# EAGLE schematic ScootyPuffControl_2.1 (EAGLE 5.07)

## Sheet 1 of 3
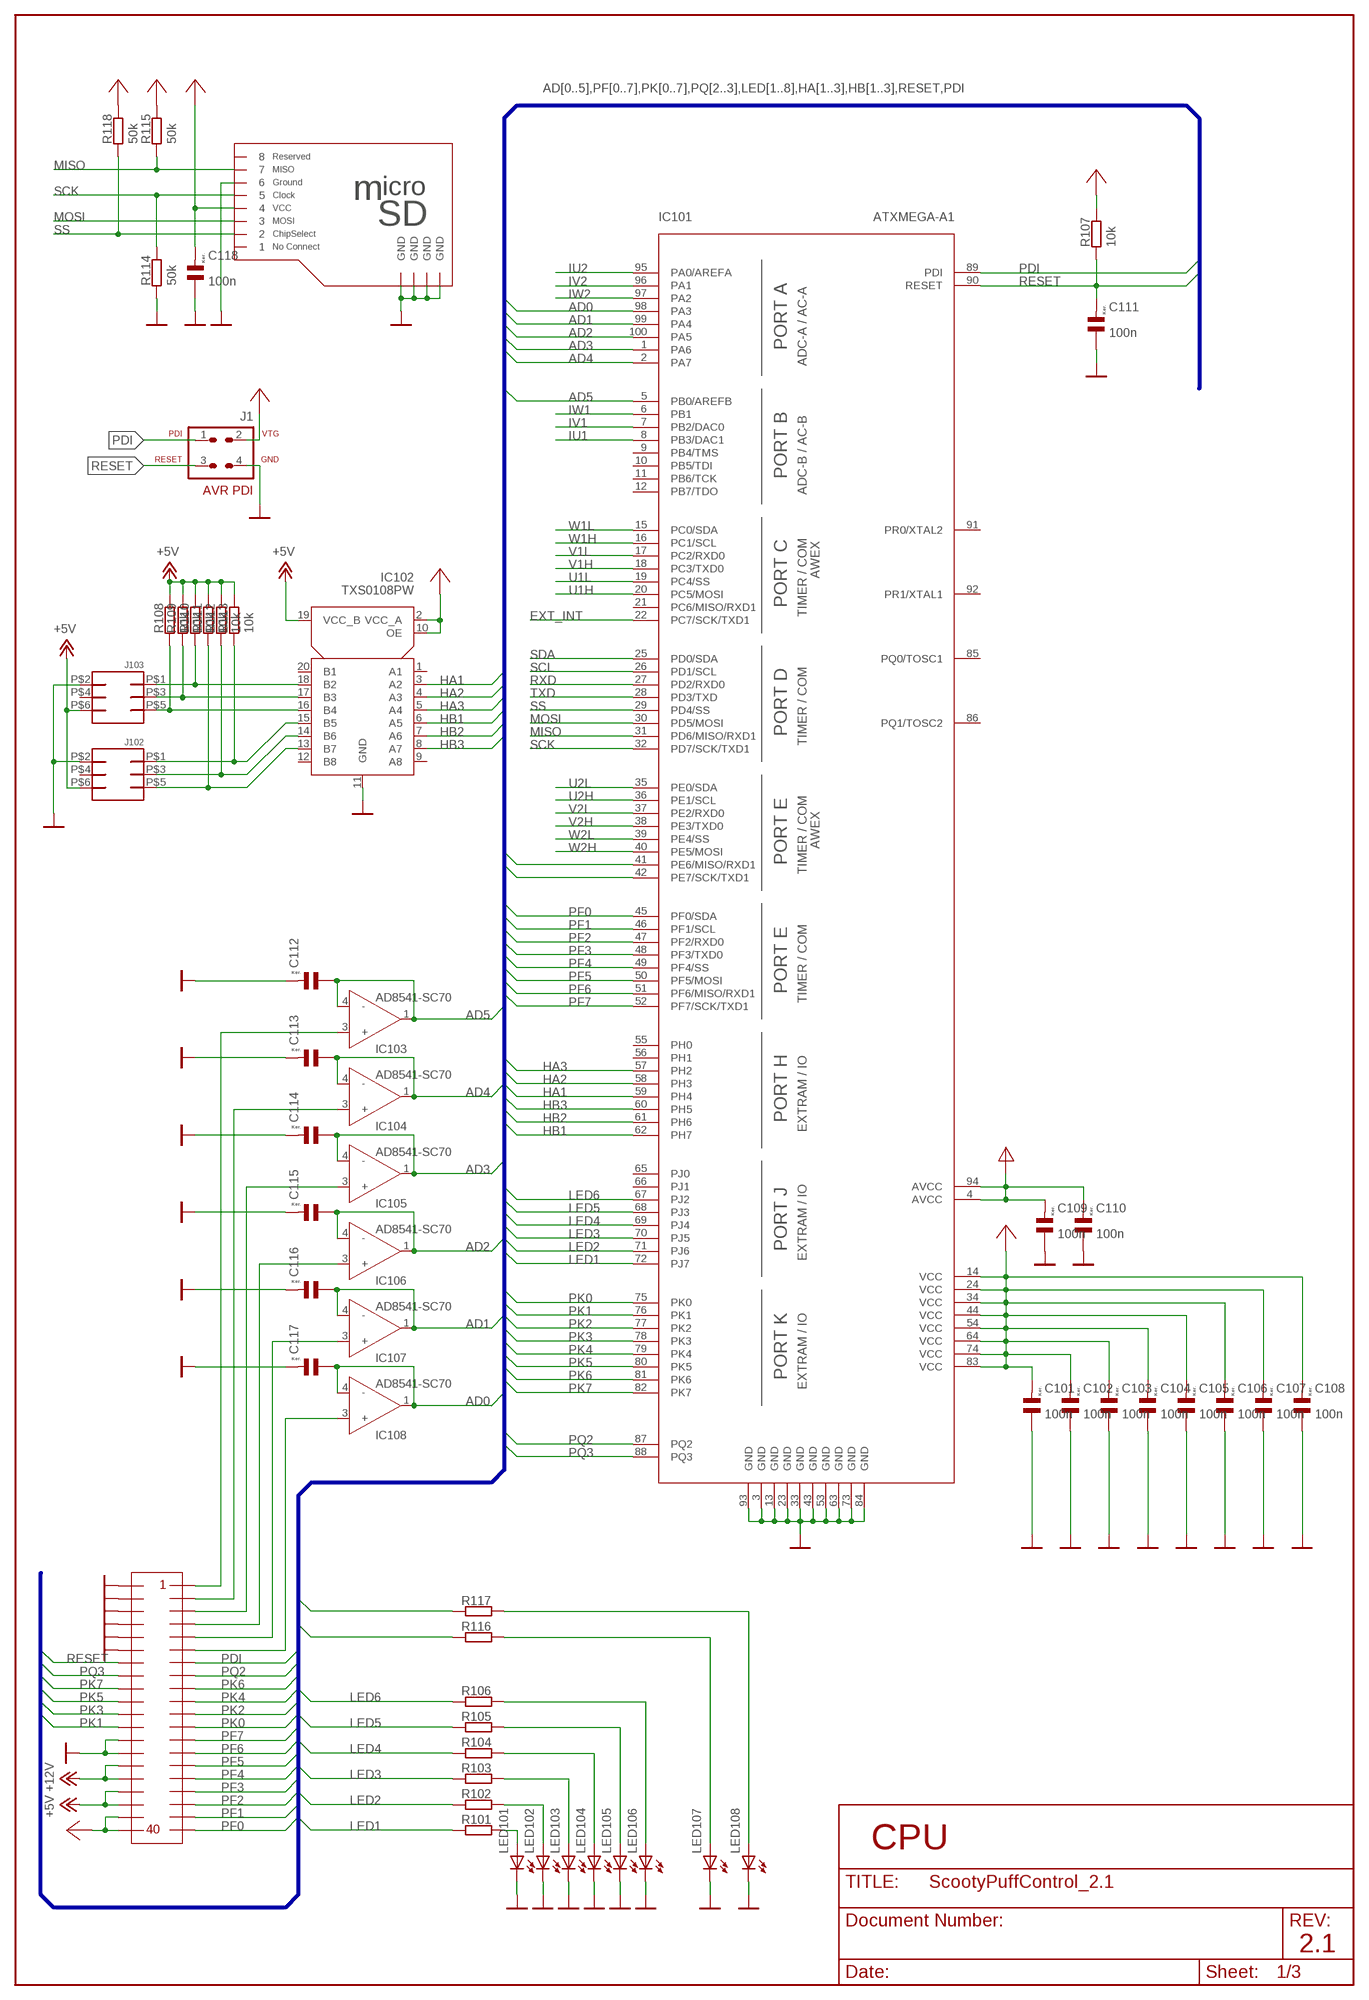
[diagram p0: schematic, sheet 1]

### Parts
C101  100n  C_KER_0805  [C0805K]
C102  100n  C_KER_0805  [C0805K]
C103  100n  C_KER_0805  [C0805K]
C104  100n  C_KER_0805  [C0805K]
C105  100n  C_KER_0805  [C0805K]
C106  100n  C_KER_0805  [C0805K]
C107  100n  C_KER_0805  [C0805K]
C108  100n  C_KER_0805  [C0805K]
C109  100n  C_KER_0805  [C0805K]
C110  100n  C_KER_0805  [C0805K]
C111  100n  C_KER_0805  [C0805K]
C112  C_KER_0603  [C0603K]
C113  C_KER_0603  [C0603K]
C114  C_KER_0603  [C0603K]
C115  C_KER_0603  [C0603K]
C116  C_KER_0603  [C0603K]
C117  C_KER_0603  [C0603K]
C118  100n  C_KER_0805  [C0805K]
IC101  ATXMEGA-A1  [TQFP100]
IC102  TXS0108PW  TXB0108PW  [TSSOP20]
IC103  AD8541-SC70  [SC70-5L]
IC104  AD8541-SC70  [SC70-5L]
IC105  AD8541-SC70  [SC70-5L]
IC106  AD8541-SC70  [SC70-5L]
IC107  AD8541-SC70  [SC70-5L]
IC108  AD8541-SC70  [SC70-5L]
J1  AVR-PDIMM04  [SMDTOP4]
J100  SCOOTYPUFF_EXTENSION  SCOOTYPUFF_EXTENSION_SMT  [SCOOTYPUFF_EXTENSION_SMT]
J102  SL6X2_SL  [SL2X3G_SMD254@1]
J103  SL6X2_SL  [SL2X3G_SMD254@1]
J104  MICRO_SD_ST1  [JAE_ST1_MICOSD]
LED101  LEDCHIP-LED0805  [CHIP-LED0805]
LED102  LEDCHIP-LED0805  [CHIP-LED0805]
LED103  LEDCHIP-LED0805  [CHIP-LED0805]
LED104  LEDCHIP-LED0805  [CHIP-LED0805]
LED105  LEDCHIP-LED0805  [CHIP-LED0805]
LED106  LEDCHIP-LED0805  [CHIP-LED0805]
LED107  LEDCHIP-LED0805  [CHIP-LED0805]
LED108  LEDCHIP-LED0805  [CHIP-LED0805]
R101  R_0805  [R0805]
R102  R_0805  [R0805]
R103  R_0805  [R0805]
R104  R_0805  [R0805]
R105  R_0805  [R0805]
R106  R_0805  [R0805]
R107  10k  R_0805  [R0805]
R108  10k  R_0603  [R0603]
R109  10k  R_0603  [R0603]
R110  10k  R_0603  [R0603]
R111  10k  R_0603  [R0603]
R112  10k  R_0603  [R0603]
R113  10k  R_0603  [R0603]
R114  50k  R_0805  [R0805]
R115  50k  R_0805  [R0805]
R116  R_0805  [R0805]
R117  R_0805  [R0805]
R118  50k  R_0805  [R0805]

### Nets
+5V: IC102.19(VCC_B) J100.P$34 J100.P$36 J102.P$6 J103.P$6 R108.2 R109.2 R110.2 R111.2 R112.2 R113.2 ; also sheet 3
+12V: J100.P$30 J100.P$32 ; also sheet 2,3
AD0: C117.1 IC101.98(PA3) IC108.1(O) IC108.4(-)
AD1: C116.1 IC101.99(PA4) IC107.1(O) IC107.4(-)
AD2: C115.1 IC101.100(PA5) IC106.1(O) IC106.4(-)
AD3: C114.1 IC101.1(PA6) IC105.1(O) IC105.4(-)
AD4: C113.1 IC101.2(PA7) IC104.1(O) IC104.4(-)
AD5: C112.1 IC101.5(PB0/AREFB) IC103.1(O) IC103.4(-)
AVCC: C109.2 C110.2 IC101.4(AVCC) IC101.94(AVCC) ; also sheet 3
EXT_INT: IC101.22(PC7/SCK/TXD1) ; also sheet 3
GND: C101.1 C102.1 C103.1 C104.1 C105.1 C106.1 C107.1 C108.1 C109.1 C110.1 C111.1 C112.2 C113.2 C114.2 C115.2 C116.2 C117.2 C118.1 IC101.3(GND) IC101.13(GND) IC101.23(GND) IC101.33(GND) IC101.43(GND) IC101.53(GND) IC101.63(GND) IC101.73(GND) IC101.84(GND) IC101.93(GND) IC102.11(GND) J1.4(GND) J100.P$2 J100.P$4 J100.P$6 J100.P$8 J100.P$10 J100.P$12 J100.P$26 J100.P$28 J102.P$2 J103.P$2 J104.6 J104.GND1(GND) J104.GND2(GND) J104.GND3(GND) J104.GND4(GND) LED101.C LED102.C LED103.C LED104.C LED105.C LED106.C LED107.C LED108.C R114.1 ; also sheet 2,3
HA1: IC101.59(PH4) IC102.3(A2)
HA2: IC101.58(PH3) IC102.4(A3)
HA3: IC101.57(PH2) IC102.5(A4)
HB1: IC101.62(PH7) IC102.6(A5)
HB2: IC101.61(PH6) IC102.7(A6)
HB3: IC101.60(PH5) IC102.8(A7)
IU1: IC101.8(PB3/DAC1) ; also sheet 2
IU2: IC101.95(PA0/AREFA) ; also sheet 2
IV1: IC101.7(PB2/DAC0) ; also sheet 2
IV2: IC101.96(PA1) ; also sheet 2
IW1: IC101.6(PB1) ; also sheet 2
IW2: IC101.97(PA2) ; also sheet 2
LED1: IC101.72(PJ7) R101.2
LED2: IC101.71(PJ6) R102.2
LED3: IC101.70(PJ5) R103.2
LED4: IC101.69(PJ4) R104.2
LED5: IC101.68(PJ3) R105.2
LED6: IC101.67(PJ2) R106.2
LED7: IC101.41(PE6/MISO/RXD1) R116.2
LED8: IC101.42(PE7/SCK/TXD1) R117.2
MISO: IC101.31(PD6/MISO/RXD1) J104.7 R115.1
MOSI: IC101.30(PD5/MOSI) J104.3
N$1: LED107.A R116.1
N$2: LED108.A R117.1
N$21: IC107.3(+) J100.P$9
N$35: IC102.18(B2) J103.P$1 R110.1
N$36: IC102.16(B4) J103.P$5 R108.1
N$37: IC102.17(B3) J103.P$3 R109.1
N$39: IC102.15(B5) J102.P$1 R113.1
N$40: IC102.14(B6) J102.P$3 R112.1
N$41: IC102.13(B7) J102.P$5 R111.1
N$63: LED101.A R101.1
N$64: IC108.3(+) J100.P$11
N$65: IC106.3(+) J100.P$7
N$66: IC105.3(+) J100.P$5
N$67: IC104.3(+) J100.P$3
N$68: IC103.3(+) J100.P$1
N$70: LED102.A R102.1
N$71: LED103.A R103.1
N$72: LED104.A R104.1
N$73: LED105.A R105.1
N$74: LED106.A R106.1
PDI: IC101.89(PDI) J1.1(PDI) J100.P$13
PF0: IC101.45(PF0/SDA) J100.P$39
PF1: IC101.46(PF1/SCL) J100.P$37
PF2: IC101.47(PF2/RXD0) J100.P$35
PF3: IC101.48(PF3/TXD0) J100.P$33
PF4: IC101.49(PF4/SS) J100.P$31
PF5: IC101.50(PF5/MOSI) J100.P$29
PF6: IC101.51(PF6/MISO/RXD1) J100.P$27
PF7: IC101.52(PF7/SCK/TXD1) J100.P$25
PK0: IC101.75(PK0) J100.P$23
PK1: IC101.76(PK1) J100.P$24
PK2: IC101.77(PK2) J100.P$21
PK3: IC101.78(PK3) J100.P$22
PK4: IC101.79(PK4) J100.P$19
PK5: IC101.80(PK5) J100.P$20
PK6: IC101.81(PK6) J100.P$17
PK7: IC101.82(PK7) J100.P$18
PQ2: IC101.87(PQ2) J100.P$15
PQ3: IC101.88(PQ3) J100.P$16
RESET: C111.2 IC101.90(RESET) J1.3(RESET) J100.P$14 R107.1
RXD: IC101.27(PD2/RXD0)
SCK: IC101.32(PD7/SCK/TXD1) J104.5 R114.2
SCL: IC101.26(PD1/SCL) ; also sheet 3
SDA: IC101.25(PD0/SDA) ; also sheet 3
SS: IC101.29(PD4/SS) J104.2 R118.1
TXD: IC101.28(PD3/TXD)
U1H: IC101.20(PC5/MOSI) ; also sheet 2
U1L: IC101.19(PC4/SS) ; also sheet 2
U2H: IC101.36(PE1/SCL) ; also sheet 2
U2L: IC101.35(PE0/SDA) ; also sheet 2
V1H: IC101.18(PC3/TXD0) ; also sheet 2
V1L: IC101.17(PC2/RXD0) ; also sheet 2
V2H: IC101.38(PE3/TXD0) ; also sheet 2
V2L: IC101.37(PE2/RXD0) ; also sheet 2
VCC: C101.2 C102.2 C103.2 C104.2 C105.2 C106.2 C107.2 C108.2 C118.2 IC101.14(VCC) IC101.24(VCC) IC101.34(VCC) IC101.44(VCC) IC101.54(VCC) IC101.64(VCC) IC101.74(VCC) IC101.83(VCC) IC102.2(VCC_A) IC102.10(OE) J1.2(VTG) J100.P$38 J100.P$40 J104.4 R107.2 R115.2 R118.2 ; also sheet 2,3
W1H: IC101.16(PC1/SCL) ; also sheet 2
W1L: IC101.15(PC0/SDA) ; also sheet 2
W2H: IC101.40(PE5/MOSI) ; also sheet 2
W2L: IC101.39(PE4/SS) ; also sheet 2
Unconnected: IC101.9(PB4/TMS) IC101.10(PB5/TDI) IC101.11(PB6/TCK) IC101.12(PB7/TDO) IC101.21(PC6/MISO/RXD1) IC101.55(PH0) IC101.56(PH1) IC101.65(PJ0) IC101.66(PJ1) IC101.85(PQ0/TOSC1) IC101.86(PQ1/TOSC2) IC101.91(PR0/XTAL2) IC101.92(PR1/XTAL1) IC102.1(A1) IC102.9(A8) IC102.12(B8) IC102.20(B1) J102.P$4 J103.P$4 J104.1 J104.8

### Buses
AD[0..5],PF[0..7],PK[0..7],PQ[2..3],LED[1..8],HA[1..3],HB[1..3],RESET,PDI

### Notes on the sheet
- CPU
- 2.1

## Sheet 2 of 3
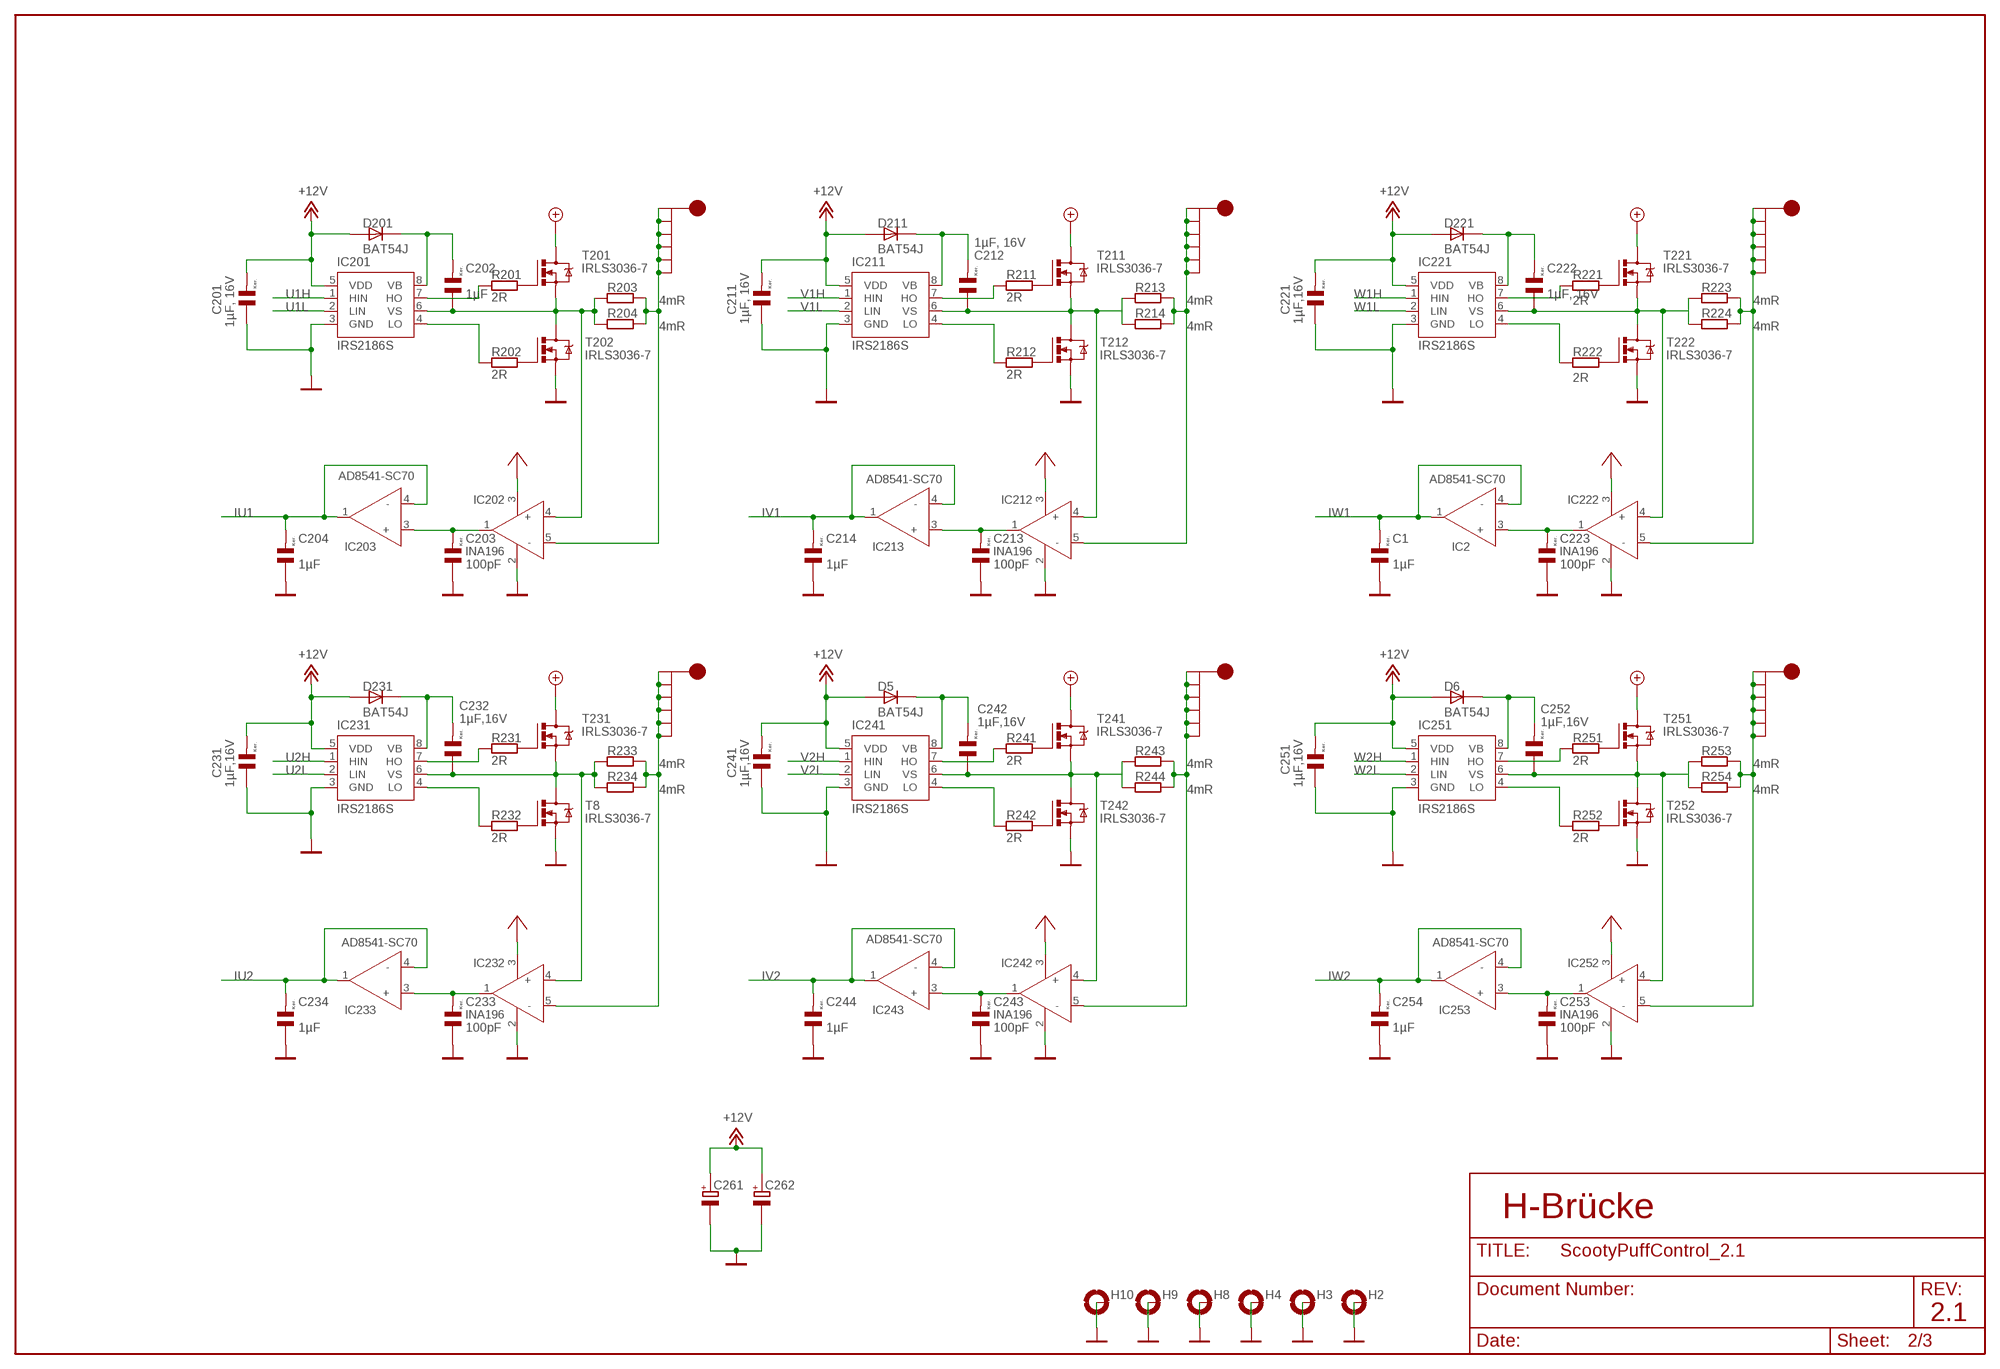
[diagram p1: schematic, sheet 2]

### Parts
C1  1µF  C_KER_0603  [C0603K]
C201  1µF, 16V  C_KER_1206  [C1206K]
C202  1µF  C_KER_1206  [C1206K]
C203  100pF  C_KER_0603  [C0603K]
C204  1µF  C_KER_0603  [C0603K]
C211  1µF, 16V  C_KER_1206  [C1206K]
C212  1µF, 16V  C_KER_1206  [C1206K]
C213  100pF  C_KER_0603  [C0603K]
C214  1µF  C_KER_0603  [C0603K]
C221  1µF,16V  C_KER_1206  [C1206K]
C222  1µF, 16V  C_KER_1206  [C1206K]
C223  100pF  C_KER_0603  [C0603K]
C231  1µF,16V  C_KER_1206  [C1206K]
C232  1µF,16V  C_KER_1206  [C1206K]
C233  100pF  C_KER_0603  [C0603K]
C234  1µF  C_KER_0603  [C0603K]
C241  1µF,16V  C_KER_1206  [C1206K]
C242  1µF,16V  C_KER_1206  [C1206K]
C243  100pF  C_KER_0603  [C0603K]
C244  1µF  C_KER_0603  [C0603K]
C251  1µF,16V  C_KER_1206  [C1206K]
C252  1µF,16V  C_KER_1206  [C1206K]
C253  100pF  C_KER_0603  [C0603K]
C254  1µF  C_KER_0603  [C0603K]
C261  ELKO_SMD_D  [SMC_D]
C262  ELKO_SMD_D  [SMC_D]
D5  BAT54J  DIODE  [SOD323-W]
D6  BAT54J  DIODE  [SOD323-W]
D201  BAT54J  DIODE  [SOD323-W]
D211  BAT54J  DIODE  [SOD323-W]
D221  BAT54J  DIODE  [SOD323-W]
D231  BAT54J  DIODE  [SOD323-W]
H2  MOUNT-PAD-ROUND3.2  [3,2-PAD]
H3  MOUNT-PAD-ROUND3.2  [3,2-PAD]
H4  MOUNT-PAD-ROUND3.2  [3,2-PAD]
H8  MOUNT-PAD-ROUND3.2  [3,2-PAD]
H9  MOUNT-PAD-ROUND3.2  [3,2-PAD]
H10  MOUNT-PAD-ROUND3.2  [3,2-PAD]
IC2  AD8541-SC70  [SC70-5L]
IC201  IRS2186S  [SO08]
IC202  INA196  [SOT23-5L]
IC203  AD8541-SC70  [SC70-5L]
IC211  IRS2186S  [SO08]
IC212  INA196  [SOT23-5L]
IC213  AD8541-SC70  [SC70-5L]
IC221  IRS2186S  [SO08]
IC222  INA196  [SOT23-5L]
IC231  IRS2186S  [SO08]
IC232  INA196  [SOT23-5L]
IC233  AD8541-SC70  [SC70-5L]
IC241  IRS2186S  [SO08]
IC242  INA196  [SOT23-5L]
IC243  AD8541-SC70  [SC70-5L]
IC251  IRS2186S  [SO08]
IC252  INA196  [SOT23-5L]
IC253  AD8541-SC70  [SC70-5L]
J_U1  WE-SVB-6  [WE-SVB-6]
J_U2  WE-SVB-6  [WE-SVB-6]
J_V1  WE-SVB-6  [WE-SVB-6]
J_V2  WE-SVB-6  [WE-SVB-6]
J_W1  WE-SVB-6  [WE-SVB-6]
J_W2  WE-SVB-6  [WE-SVB-6]
R201  2R  R_0805  [R0805]
R202  2R  R_0805  [R0805]
R203  4mR  R_2010  [R2010]
R204  4mR  R_2010  [R2010]
R211  2R  R_0805  [R0805]
R212  2R  R_0805  [R0805]
R213  4mR  R_2010  [R2010]
R214  4mR  R_2010  [R2010]
R221  2R  R_0805  [R0805]
R222  2R  R_0805  [R0805]
R223  4mR  R_2010  [R2010]
R224  4mR  R_2010  [R2010]
R231  2R  R_0805  [R0805]
R232  2R  R_0805  [R0805]
R233  4mR  R_2010  [R2010]
R234  4mR  R_2010  [R2010]
R241  2R  R_0805  [R0805]
R242  2R  R_0805  [R0805]
R243  4mR  R_2010  [R2010]
R244  4mR  R_2010  [R2010]
R251  2R  R_0805  [R0805]
R252  2R  R_0805  [R0805]
R253  4mR  R_2010  [R2010]
R254  4mR  R_2010  [R2010]
T8  IRLS3036-7  [D2PACK-7P]
T201  IRLS3036-7  [D2PACK-7P]
T202  IRLS3036-7  [D2PACK-7P]
T211  IRLS3036-7  [D2PACK-7P]
T212  IRLS3036-7  [D2PACK-7P]
T221  IRLS3036-7  [D2PACK-7P]
T222  IRLS3036-7  [D2PACK-7P]
T231  IRLS3036-7  [D2PACK-7P]
T241  IRLS3036-7  [D2PACK-7P]
T242  IRLS3036-7  [D2PACK-7P]
T251  IRLS3036-7  [D2PACK-7P]
T252  IRLS3036-7  [D2PACK-7P]

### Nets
+12V: C201.2 C211.2 C221.2 C231.2 C241.2 C251.2 C261.+ C262.+ D5.A D6.A D201.A D211.A D221.A D231.A IC201.5(VDD) IC211.5(VDD) IC221.5(VDD) IC231.5(VDD) IC241.5(VDD) IC251.5(VDD) ; also sheet 1,3
GND: C1.1 C201.1 C203.1 C204.1 C211.1 C213.1 C214.1 C221.1 C223.1 C231.1 C233.1 C234.1 C241.1 C243.1 C244.1 C251.1 C253.1 C254.1 C261.- C262.- H2.B3,2(MOUNT) H3.B3,2(MOUNT) H4.B3,2(MOUNT) H8.B3,2(MOUNT) H9.B3,2(MOUNT) H10.B3,2(MOUNT) IC201.3(GND) IC202.2(GND) IC211.3(GND) IC212.2(GND) IC221.3(GND) IC222.2(GND) IC231.3(GND) IC232.2(GND) IC241.3(GND) IC242.2(GND) IC251.3(GND) IC252.2(GND) T8.S T202.S T212.S T222.S T242.S T252.S ; also sheet 1,3
IU1: C204.2 IC203.1(O) IC203.4(-) ; also sheet 1
IU2: C234.2 IC233.1(O) IC233.4(-) ; also sheet 1
IV1: C214.2 IC213.1(O) IC213.4(-) ; also sheet 1
IV2: C244.2 IC243.1(O) IC243.4(-) ; also sheet 1
IW1: C1.2 IC2.1(O) IC2.4(-) ; also sheet 1
IW2: C254.2 IC253.1(O) IC253.4(-) ; also sheet 1
N$4: IC201.7(HO) R201.1
N$5: IC201.4(LO) R202.1
N$6: IC211.4(LO) R212.1
N$7: IC211.7(HO) R211.1
N$9: IC221.4(LO) R222.1
N$10: IC221.7(HO) R221.1
N$11: C212.2 D211.C IC211.8(VB)
N$12: C202.2 D201.C IC201.8(VB)
N$14: C222.2 D221.C IC221.8(VB)
N$42: IC231.7(HO) R231.1
N$43: IC231.4(LO) R232.1
N$44: IC241.4(LO) R242.1
N$45: IC241.7(HO) R241.1
N$46: IC251.4(LO) R252.1
N$47: IC251.7(HO) R251.1
N$48: C232.2 D231.C IC231.8(VB)
N$49: C242.2 D5.C IC241.8(VB)
N$50: C252.2 D6.C IC251.8(VB)
N$51: R201.2 T201.G
N$52: R202.2 T202.G
N$53: R211.2 T211.G
N$54: R212.2 T212.G
N$55: R221.2 T221.G
N$56: R222.2 T222.G
N$57: R232.2 T8.G
N$58: R231.2 T231.G
N$59: R241.2 T241.G
N$60: R242.2 T242.G
N$61: R251.2 T251.G
N$62: R252.2 T252.G
N$69: C233.2 IC232.1(O) IC233.3(+)
N$75: C223.2 IC2.3(+) IC222.1(O)
N$76: C203.2 IC202.1(O) IC203.3(+)
N$77: C243.2 IC242.1(O) IC243.3(+)
N$80: C213.2 IC212.1(O) IC213.3(+)
N$81: C253.2 IC252.1(O) IC253.3(+)
U1: C202.1 IC201.6(VS) IC202.4(+) R203.P$1 R204.P$1 T201.S T202.D
U1H: IC201.1(HIN) ; also sheet 1
U1L: IC201.2(LIN) ; also sheet 1
U1O: IC202.5(-) J_U1.P$1 J_U1.P$2 J_U1.P$3 J_U1.P$4 J_U1.P$5 J_U1.P$6 R203.P$2 R204.P$2
U2: C232.1 IC231.6(VS) IC232.4(+) R233.P$1 R234.P$1 T8.D T231.S
U2H: IC231.1(HIN) ; also sheet 1
U2L: IC231.2(LIN) ; also sheet 1
U2O: IC232.5(-) J_U2.P$1 J_U2.P$2 J_U2.P$3 J_U2.P$4 J_U2.P$5 J_U2.P$6 R233.P$2 R234.P$2
V1: C212.1 IC211.6(VS) IC212.4(+) R213.P$1 R214.P$1 T211.S T212.D
V1H: IC211.1(HIN) ; also sheet 1
V1L: IC211.2(LIN) ; also sheet 1
V1O: IC212.5(-) J_V1.P$1 J_V1.P$2 J_V1.P$3 J_V1.P$4 J_V1.P$5 J_V1.P$6 R213.P$2 R214.P$2
V2: C242.1 IC241.6(VS) IC242.4(+) R243.P$1 R244.P$1 T241.S T242.D
V2H: IC241.1(HIN) ; also sheet 1
V2L: IC241.2(LIN) ; also sheet 1
V2O: IC242.5(-) J_V2.P$1 J_V2.P$2 J_V2.P$3 J_V2.P$4 J_V2.P$5 J_V2.P$6 R243.P$2 R244.P$2
VCC: IC202.3(VCC) IC212.3(VCC) IC222.3(VCC) IC232.3(VCC) IC242.3(VCC) IC252.3(VCC) ; also sheet 1,3
VS: T201.D T211.D T221.D T231.D T241.D T251.D ; also sheet 3
W1: C222.1 IC221.6(VS) IC222.4(+) R223.P$1 R224.P$1 T221.S T222.D
W1H: IC221.1(HIN) ; also sheet 1
W1L: IC221.2(LIN) ; also sheet 1
W1O: IC222.5(-) J_W1.P$1 J_W1.P$2 J_W1.P$3 J_W1.P$4 J_W1.P$5 J_W1.P$6 R223.P$2 R224.P$2
W2: C252.1 IC251.6(VS) IC252.4(+) R253.P$1 R254.P$1 T251.S T252.D
W2H: IC251.1(HIN) ; also sheet 1
W2L: IC251.2(LIN) ; also sheet 1
W2O: IC252.5(-) J_W2.P$1 J_W2.P$2 J_W2.P$3 J_W2.P$4 J_W2.P$5 J_W2.P$6 R253.P$2 R254.P$2

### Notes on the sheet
- H-Brücke
- 2.1

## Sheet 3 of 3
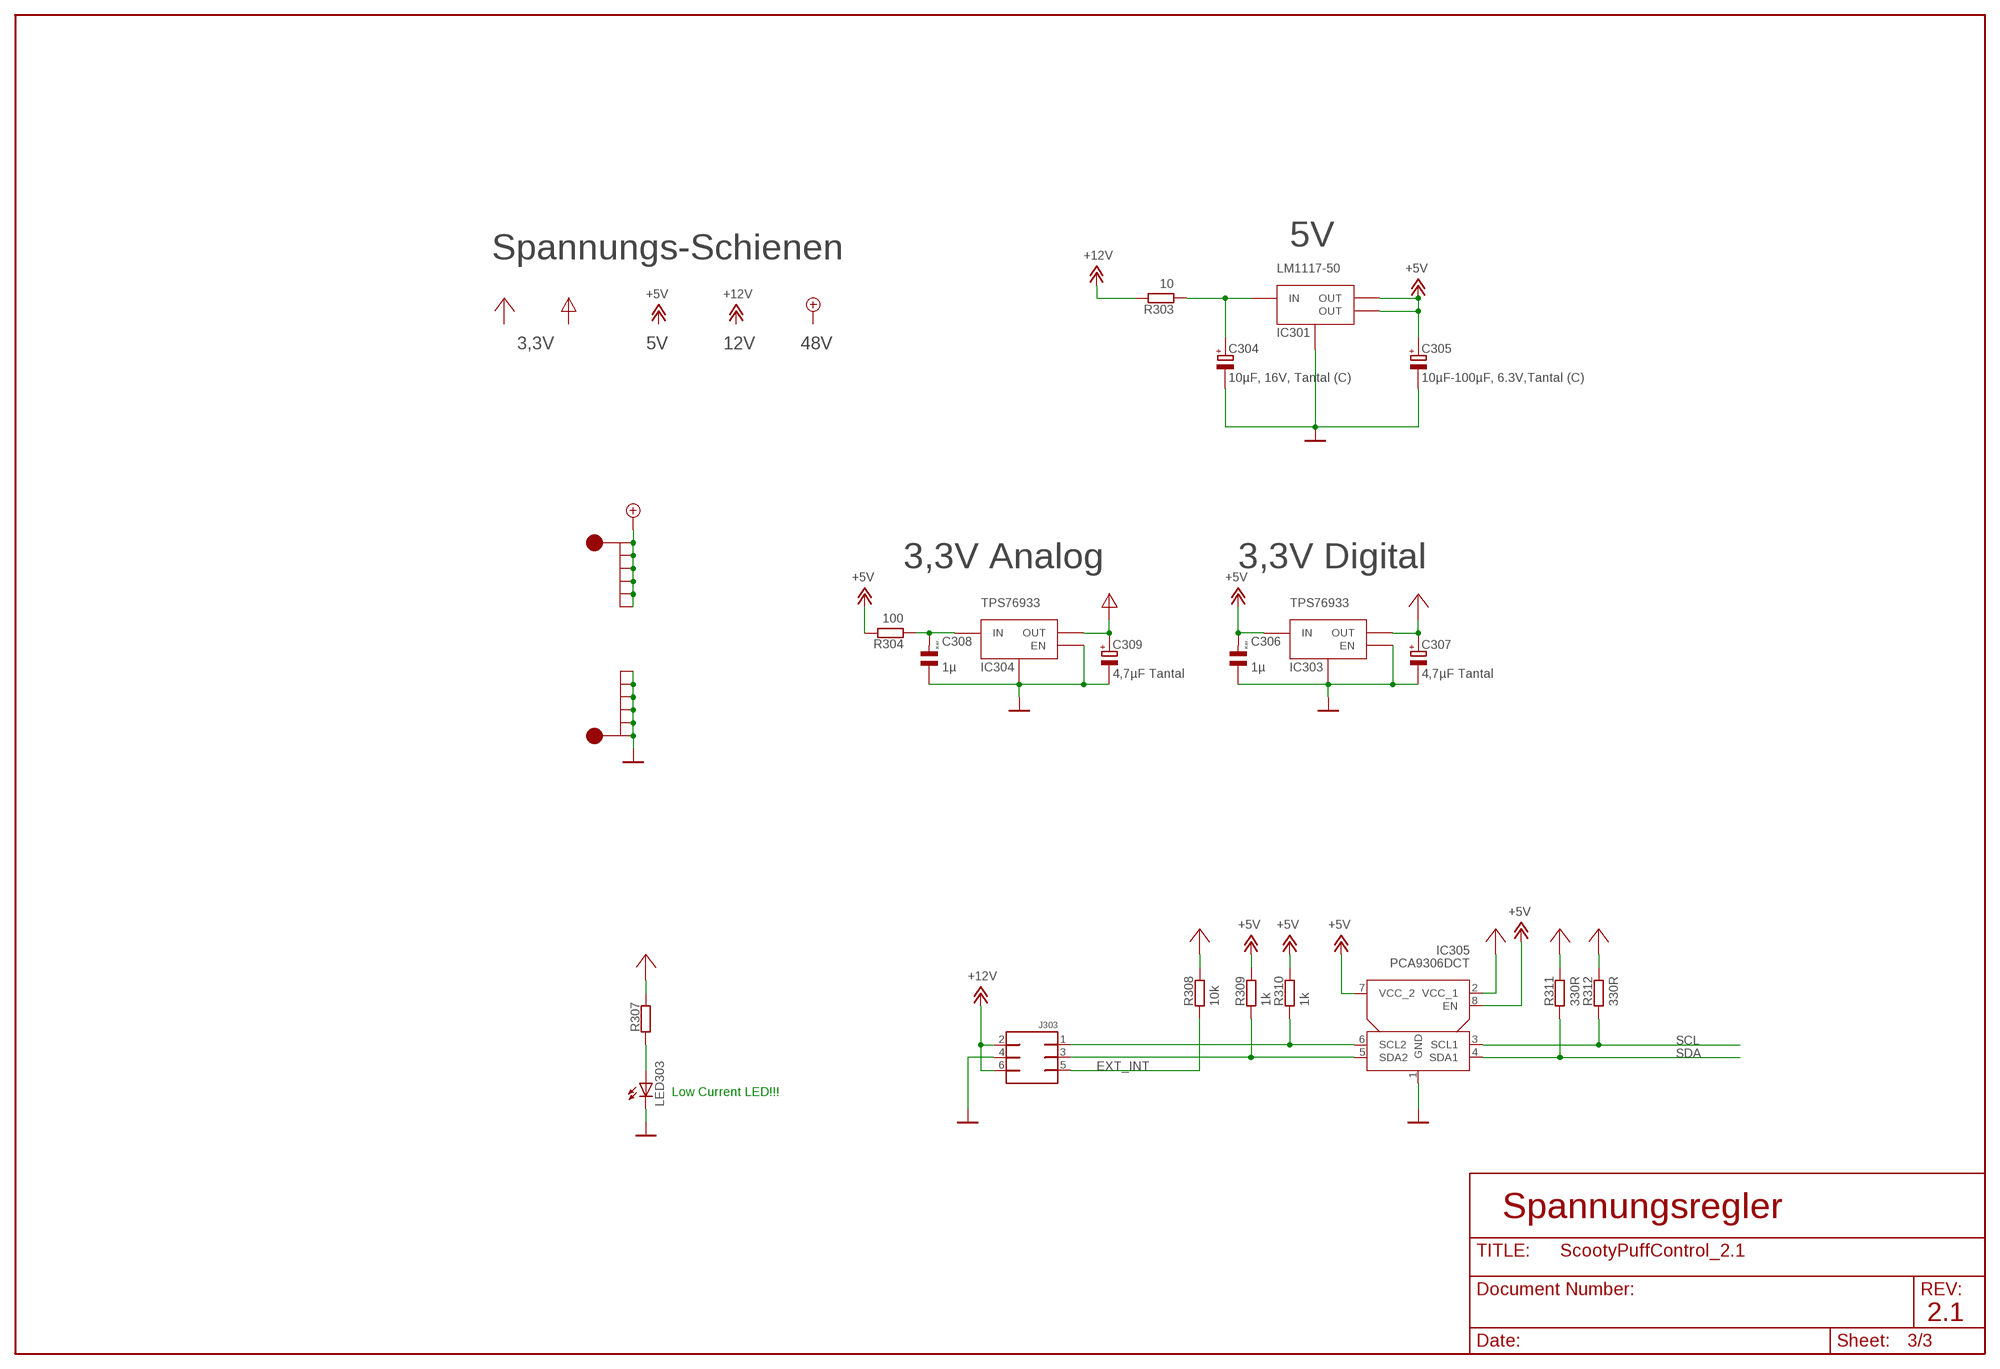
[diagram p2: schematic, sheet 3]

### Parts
C304  10µF, 16V, Tantal (C)  ELKO_SMD_C  [SMC_C]
C305  10µF-100µF, 6.3V,Tantal (C)  ELKO_SMD_C  [SMC_C]
C306  1µ  C_KER_0805  [C0805K]
C307  4,7µF Tantal  ELKO_SMD_A  [SMC_A]
C308  1µ  C_KER_0805  [C0805K]
C309  4,7µF Tantal  ELKO_SMD_A  [SMC_A]
IC301  LM1117-50  [SOT223]
IC303  TPS76933  [SOT23-5L]
IC304  TPS76933  [SOT23-5L]
IC305  PCA9306DCT  [SSOP08]
J301  WE-SVB-6  [WE-SVB-6]
J302  WE-SVB-6  [WE-SVB-6]
J303  SL3X2_SL  [SL2X3G_SMD254]
LED303  LEDCHIP-LED0805  [CHIP-LED0805]
R303  10  R_1206  [R1206]
R304  100  R_0805  [R0805]
R307  R_0805  [R0805]
R308  10k  R_0805  [R0805]
R309  1k  R_0805  [R0805]
R310  1k  R_0805  [R0805]
R311  330R  R_0805  [R0805]
R312  330R  R_0805  [R0805]

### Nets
+5V: C305.+ C306.2 IC301.2(OUT) IC301.4(OUT) IC303.1(IN) IC305.7(VCC_2) IC305.8(EN) R304.2 R309.2 R310.2 ; also sheet 1
+12V: J303.2 J303.6 R303.2 ; also sheet 1,2
AVCC: C309.+ IC304.5(OUT) ; also sheet 1
EXT_INT: J303.5 R308.1 ; also sheet 1
GND: C304.- C305.- C306.1 C307.- C308.1 C309.- IC301.1(GND) IC303.2(GND) IC303.3(EN) IC304.2(GND) IC304.3(EN) IC305.1(GND) J302.P$1 J302.P$2 J302.P$3 J302.P$4 J302.P$5 J302.P$6 J303.4 LED303.C ; also sheet 1,2
N$8: LED303.A R307.1
N$30: IC305.6(SCL2) J303.1 R310.1
N$33: C304.+ IC301.3(IN) R303.1
N$34: C308.2 IC304.1(IN) R304.1
N$78: IC305.5(SDA2) J303.3 R309.1
SCL: IC305.3(SCL1) R312.1 ; also sheet 1
SDA: IC305.4(SDA1) R311.1 ; also sheet 1
VCC: C307.+ IC303.5(OUT) IC305.2(VCC_1) R307.2 R308.2 R311.2 R312.2 ; also sheet 1,2
VS: J301.P$1 J301.P$2 J301.P$3 J301.P$4 J301.P$5 J301.P$6 ; also sheet 2

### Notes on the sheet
- 5V
- Spannungs-Schienen
- 3,3V | 5V | 12V | 48V
- 3,3V Analog | 3,3V Digital
- Low Current LED!!!
- Spannungsregler
- 2.1

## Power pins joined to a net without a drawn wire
GND: IC2.2(GND) IC103.2(GND) IC104.2(GND) IC105.2(GND) IC106.2(GND) IC107.2(GND) IC108.2(GND) IC203.2(GND) IC213.2(GND) IC233.2(GND) IC243.2(GND) IC253.2(GND)
VCC: IC2.5(VCC) IC103.5(VCC) IC104.5(VCC) IC105.5(VCC) IC106.5(VCC) IC107.5(VCC) IC108.5(VCC) IC203.5(VCC) IC213.5(VCC) IC233.5(VCC) IC243.5(VCC) IC253.5(VCC)

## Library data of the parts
C1 C101-C118 C201-C204 C211-C214 C221-C223 C231-C234 C241-C244 C251-C254 C306 C308 = lib-rcl:C_KER
C261 C262 C304 C305 C307 C309 = lib-rcl:ELKO
D5 D6 D201 D211 D221 D231 = lib-halbleiter:DIODE
H2-H4 H8-H10 = holes:MOUNT-PAD-ROUND: MOUNTING PAD, round
IC2 IC103-IC108 IC203 IC213 IC233 IC243 IC253 = lib-ic:AD8541
IC101 = lib-avr:ATXMEGA-A1
IC102 = lib-ic:TXB0108?
IC201 IC211 IC221 IC231 IC241 IC251 = lib-ic:IRS2186?
IC202 IC212 IC222 IC232 IC242 IC252 = lib-ic:INA19?; G20: G=20
IC301 = lib-ic:LM1117-*: Alternativ auch TLV1117 von TI
IC303 IC304 = lib-ic:TPS769*
IC305 = lib-ic:PCA9306
J1 = lib-avr:AVR-PDI
J100 = lib-misc:SCOOTYPUFF_EXTENSION
J102 J103 = lib-connectors:SL6X2?
J104 = lib-misc:MICRO_SD
J301 J302 J_U1 J_U2 J_V1 J_V2 J_W1 J_W2 = lib-connectors:WE-SVB-6
J303 = lib-connectors:SL3X2?
LED101-LED108 LED303 = lib-halbleiter:LED
R101-R118 R201-R204 R211-R214 R221-R224 R231-R234 R241-R244 R251-R254 R303 R304 R307-R312 = lib-rcl:R: RESISTOR, European symbol
T8 T201 T202 T211 T212 T221 T222 T231 T241 T242 T251 T252 = lib-halbleiter:IRLS3036-7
